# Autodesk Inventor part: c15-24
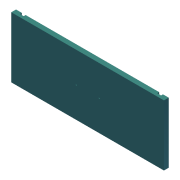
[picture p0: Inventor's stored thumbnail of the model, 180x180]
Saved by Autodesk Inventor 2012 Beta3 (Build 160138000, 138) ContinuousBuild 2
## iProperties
Created: 2011-02
Part Number: c15-24
Material: Default
Document SubType Name: Modeling
Designer: Beta-8540w
Density: 1 g/cm^3
Author: Beta-8540w
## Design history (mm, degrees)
sketch "Sketch1"
  geometry: L1 (-253, -100.6)-(253, -100.6); L2 (253, -100.6)-(253, 100.6); L3 (253, 100.6)-(-253, 100.6); L4 (-253, 100.6)-(-253, -100.6); 3 further points
  constraints: 8 end point, 2 midpoint, 2 parallel, 1 horizontal, 1 horizontal alignment, 1 perpendicular, 1 vertical alignment
  dimensions: "drawer_core_width" = 506 distance of L3.end L2.end (= drawer_width - 2 x edge_band_thickness); "drawer_core_height" = 201.2 distance of L2.end L1.end (= drawer_height - 2 x edge_band_thickness)
extrude "Drawer Face" new body sketch "Sketch1" distance "d2" = 15.875; taper "d3" = 0 deg
sketch "Sketch2"
  geometry: 1 further point
hole "Single Hole Pull" sketch "Sketch2" at (0, 0) diameter "d4" = 4.4958; stored, may be unused: countersink angle "d8" = 82 deg, drill point angle "d10" = 118 deg; dims "d5" = 19.05, "d6" = 8.4328, "d7" = 6.35, "d9" = 25.4
sketch "Sketch3"
  geometry: L1 (-38.1, 0)-(38.1, 0); 2 further points
  constraints: 2 end point, 1 coincident, 1 horizontal, 1 midpoint
  dimensions: "pull_width" = 76.2 distance of L1.start L1.end
hole "Double Hole Pull" sketch "Sketch3" at (-38.1, 0), (38.1, 0) diameter "d12" = 4.4958; stored, may be unused: countersink angle "d16" = 82 deg, drill point angle "d18" = 118 deg; dims "d13" = 19.05, "d14" = 8.4328, "d15" = 6.35, "d17" = 25.4
sketch "Sketch4"
  geometry: L1 (253, -100.6)-(-253, -100.6) reference; L2 (253, 100.6)-(253, -100.6) reference; L3 (-253, 100.6)-(253, 100.6) reference; L4 (-253, -100.6)-(-253, 100.6) reference; L5 (-233.95, 100.6)-(-221.25, 100.6); L6 (-221.25, 100.6)-(-221.25, -100.6); L7 (-221.25, -100.6)-(-233.95, -100.6); L8 (-233.95, -100.6)-(-233.95, 100.6); L9 (233.95, 100.6)-(221.25, 100.6); L10 (221.25, 100.6)-(221.25, -100.6); L11 (221.25, -100.6)-(233.95, -100.6); L12 (233.95, -100.6)-(233.95, 100.6); 1 further point
  constraints: 16 end point, 4 parallel, 4 point on line, 2 horizontal, 2 perpendicular, 1 collinear
  dimensions: "d19" = 12.7 distance of L5.start L5.end; "d20" = 19.05 distance between parallel lines of L8 L4; "d21" = 19.05 distance between parallel lines of L2 L12 (= d20)
extrude "Side Relief" cut sketch "Sketch4" distance "d22" = 6.35; taper "d23" = 0 deg
sketch "Sketch5"
  geometry: L1 (221.25, -100.6)-(221.25, 100.6) reference; L2 (-221.25, 100.6)-(-221.25, -100.6) reference; L3 (221.25, -100.6)-(-221.25, -100.6) reference; L4 (-221.25, -90.948)-(221.25, -90.948); L5 (221.25, -90.948)-(221.25, -87.646); L6 (221.25, -87.646)-(-221.25, -87.646); L7 (-221.25, -87.646)-(-221.25, -90.948); 1 further point
  constraints: 8 end point, 2 parallel, 2 point on line, 1 horizontal, 1 perpendicular
  dimensions: "d24" = 9.652 distance between parallel lines of L3 L4; "d25" = 3.302 distance of L4.end L5.end
extrude "Bottom Relief" cut sketch "Sketch5" distance "d26" = 6.35; taper "d27" = 0 deg
body "Solid1"
other parameters: "d28" = 0, "d29" = 0, "d30" = 0, "d31" = 0, "d32" = 0, "d33" = 180 deg, "d40" = 0, "d41" = 0, "d42" = 0, "d43" = 0, "d44" = 180 deg, "d45" = 180 deg, "d46" = 0, "d47" = 0, "d48" = 0, "d49" = 0, "d50" = 180 deg, "d51" = 0, "d52" = 0, "d53" = 0, "d54" = 0, "d55" = 0, "d56" = 180 deg, "d57" = 0, "drawer_width" = 508 [user parameter; used in 1 equation term], "edge_band_thickness" = 1 [user parameter; used in 2 equation terms], "drawer_height" = 203.2 [user parameter; used in 1 equation term]
